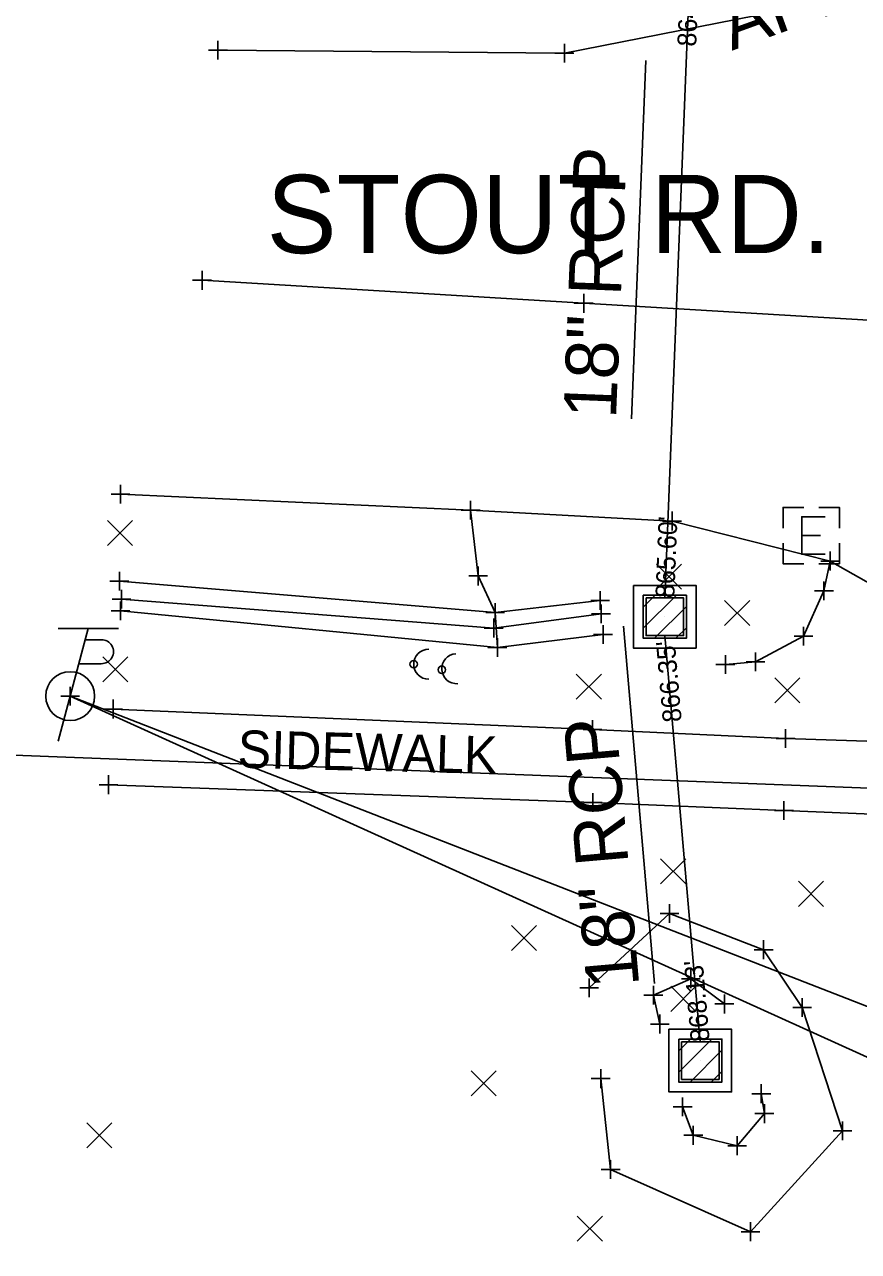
# Model space of a CAD drawing. Extents: x 1380550 to 1381945, y 468927 to 470496.
# Drawn here: x 1381538.1 to 1381582.5, y 470212.8 to 470278.1 of the extents above; entities that cross this region are included whole.
import ezdxf

# ---------------------------------------------------------------- set-up
doc = ezdxf.new("R2010")
doc.units = 0
for name, color, linetype in [('DR_X_Cells', 7, 'Continuous'), ('DR_X_Ditch', 7, 'Continuous'), ('DR_X_Storm_Sewer', 7, 'Continuous'), ('DR_X_Text', 7, 'Continuous'), ('GK_Drainage_Nodes', 7, 'Continuous'), ('HY_X_Water_Edge', 7, 'Continuous'), ('PV_X_COP', 7, 'Continuous'), ('PV_X_EOP', 7, 'Continuous'), ('PV_X_Walk', 7, 'Continuous'), ('RD_X_Text', 7, 'Continuous'), ('RW_X_Esmt_General', 7, 'Continuous'), ('SC_Scratch1', 7, 'Continuous'), ('SV_X_Random_Point', 7, 'Continuous'), ('SV_X_Shot_Marker', 7, 'Continuous'), ('SV_X_Toe_of_Slope', 7, 'Continuous'), ('SV_X_Top_of_Bank', 7, 'Continuous'), ('UT_X_Electric', 7, 'Continuous'), ('UT_X_Electric_Cells', 7, 'Continuous'), ('UT_X_Misc_Cells', 7, 'Continuous'), ('UT_X_Telecom', 7, 'Continuous')]:
    doc.layers.add(name, color=color, linetype=linetype)

msp = doc.modelspace()

# ---------------------------------------------------------------- linework, layer by layer
at = {"layer": 'DR_X_Cells'}
for p, q in [((1381571.02, 470245.963), (1381572.779, 470247.722)), ((1381571.02, 470247.094), (1381571.648, 470247.722)), ((1381571.619, 470245.43), (1381573.312, 470247.123)), ((1381572.75, 470245.43), (1381573.312, 470245.992)), ((1381572.908, 470222.344), (1381574.667, 470224.102)), ((1381572.908, 470223.475), (1381573.536, 470224.102)), ((1381573.507, 470221.811), (1381575.2, 470223.504)), ((1381574.638, 470221.811), (1381575.2, 470222.372))]:
    msp.add_line(p, q, dxfattribs=at)
for points in [[(1381570.499, 470248.243), (1381573.833, 470248.243), (1381573.833, 470244.909), (1381570.499, 470244.909)], [(1381571.02, 470247.722), (1381573.312, 470247.722), (1381573.312, 470245.43), (1381571.02, 470245.43)], [(1381571.166, 470247.576), (1381573.166, 470247.576), (1381573.166, 470245.576), (1381571.166, 470245.576)], [(1381572.387, 470224.623), (1381575.721, 470224.623), (1381575.721, 470221.29), (1381572.387, 470221.29)], [(1381572.908, 470224.102), (1381575.2, 470224.102), (1381575.2, 470221.811), (1381572.908, 470221.811)], [(1381573.054, 470223.957), (1381575.054, 470223.957), (1381575.054, 470221.957), (1381573.054, 470221.957)]]:
    msp.add_lwpolyline(points, close=True, dxfattribs=at)
at = {"layer": 'DR_X_Ditch'}
msp.add_lwpolyline([(1381543.263, 470247.518), (1381563.063, 470245.978), (1381568.771, 470246.733)], dxfattribs=at)
at = {"layer": 'DR_X_Storm_Sewer'}
for p, q in [((1381572.166, 470247.576), (1381573.515, 470281.557)), ((1381574.054, 470223.957), (1381572.166, 470245.576))]:
    msp.add_line(p, q, dxfattribs=at)
at = {"layer": 'DR_X_Text'}
for p, q in [((1381571.15, 470276.186), (1381570.393, 470257.114)), ((1381569.964, 470246.079), (1381571.624, 470227.065))]:
    msp.add_line(p, q, dxfattribs=at)
at = {"layer": 'GK_Drainage_Nodes'}
for p, q in [((1381572.166, 470248.243), (1381572.166, 470248.243)), ((1381572.166, 470247.576), (1381572.166, 470247.576)), ((1381571.166, 470246.576), (1381571.166, 470246.576)), ((1381572.166, 470246.576), (1381572.166, 470246.576)), ((1381572.166, 470246.576), (1381572.166, 470246.576)), ((1381572.166, 470246.576), (1381572.166, 470246.576)), ((1381573.166, 470246.576), (1381573.166, 470246.576)), ((1381572.166, 470245.576), (1381572.166, 470245.576)), ((1381572.166, 470244.909), (1381572.166, 470244.909)), ((1381574.054, 470224.623), (1381574.054, 470224.623)), ((1381574.054, 470223.957), (1381574.054, 470223.957)), ((1381573.054, 470222.957), (1381573.054, 470222.957)), ((1381574.054, 470222.957), (1381574.054, 470222.957)), ((1381574.054, 470222.957), (1381574.054, 470222.957)), ((1381574.054, 470222.957), (1381574.054, 470222.957)), ((1381575.054, 470222.957), (1381575.054, 470222.957)), ((1381574.054, 470221.957), (1381574.054, 470221.957)), ((1381574.054, 470221.29), (1381574.054, 470221.29))]:
    msp.add_line(p, q, dxfattribs=at)
at = {"layer": 'HY_X_Water_Edge'}
for points in [[(1381543.147, 470248.469), (1381563.136, 470246.797), (1381568.729, 470247.446)], [(1381543.21, 470246.894), (1381563.256, 470244.94), (1381568.879, 470245.63)]]:
    msp.add_lwpolyline(points, dxfattribs=at)
at = {"layer": 'PV_X_COP'}
msp.add_lwpolyline([(1381547.543, 470264.484), (1381567.85, 470263.258), (1381584.182, 470262.283), (1381603.07, 470261.395)], dxfattribs=at)
at = {"layer": 'PV_X_EOP'}
for points in [[(1381613.385, 470321.734), (1381611.102, 470303.299), (1381608.359, 470295.151), (1381605.01, 470289.924), (1381604.443, 470290.292), (1381597.807, 470284.691), (1381598.172, 470283.697), (1381591.29, 470281.389), (1381566.822, 470276.57), (1381548.391, 470276.726)], [(1381543.209, 470253.101), (1381561.835, 470252.251), (1381562.236, 470248.747), (1381563.136, 470246.797), (1381563.256, 470244.94), (1381568.879, 470245.63)], [(1381561.835, 470252.251), (1381572.55, 470251.671), (1381580.965, 470249.541)], [(1381575.388, 470244.04), (1381576.993, 470244.172), (1381579.545, 470245.54), (1381580.634, 470247.96), (1381580.965, 470249.541), (1381591.472, 470243.585), (1381595.246, 470241.001), (1381599.724, 470235.672), (1381603.295, 470229.192), (1381604.877, 470222.306), (1381604.1, 470201.731), (1381602.36, 470179.429), (1381598.627, 470125.511), (1381593.594, 470071.886), (1381589.534, 470020.646), (1381585.494, 469971.089), (1381582.039, 469928.84), (1381578.382, 469880.278), (1381576.859, 469862.024), (1381576.832, 469860.709), (1381576.155, 469857.385), (1381571.588, 469847.123), (1381563.138, 469838.251)]]:
    msp.add_lwpolyline(points, dxfattribs=at)
at = {"layer": 'PV_X_Walk'}
for points in [[(1381542.819, 470241.667), (1381568.313, 470240.569), (1381578.584, 470240.095), (1381584.519, 470239.902), (1381590.984, 470239.649), (1381591.472, 470243.585)], [(1381542.564, 470237.64), (1381568.337, 470236.695), (1381578.506, 470236.262), (1381584.487, 470236.02), (1381590.642, 470235.62), (1381587.955, 470203.415), (1381586.625, 470180.461), (1381581.932, 470126.464), (1381577.652, 470073.239), (1381573.197, 470021.541), (1381569.148, 469971.738), (1381565.643, 469929.65), (1381561.644, 469881.156), (1381560.457, 469867.318), (1381559.272, 469848.708), (1381558.347, 469840.136)]]:
    msp.add_lwpolyline(points, dxfattribs=at)
at = {"layer": 'RW_X_Esmt_General'}
msp.add_lwpolyline([(1381490.401, 469029.464), (1381590.199, 470237.184), (1380558.689, 470277.035)], dxfattribs=at)
at = {"layer": 'SV_X_Random_Point'}
for p, q in [((1381542.519, 470250.365), (1381543.853, 470251.7)), ((1381542.519, 470251.7), (1381543.853, 470250.365)), ((1381571.722, 470248.046), (1381573.056, 470249.381)), ((1381571.722, 470249.381), (1381573.056, 470248.046)), ((1381575.349, 470246.105), (1381576.683, 470247.44)), ((1381575.349, 470247.44), (1381576.683, 470246.105)), ((1381542.267, 470243.114), (1381543.601, 470244.449)), ((1381542.267, 470244.449), (1381543.601, 470243.114)), ((1381567.455, 470242.188), (1381568.789, 470243.523)), ((1381567.455, 470243.523), (1381568.789, 470242.188)), ((1381578.022, 470241.99), (1381579.356, 470243.325)), ((1381578.022, 470243.325), (1381579.356, 470241.99)), ((1381571.942, 470232.36), (1381573.276, 470233.695)), ((1381571.942, 470233.695), (1381573.276, 470232.36)), ((1381579.269, 470231.162), (1381580.603, 470232.497)), ((1381579.269, 470232.497), (1381580.603, 470231.162)), ((1381564, 470228.809), (1381565.334, 470230.144)), ((1381564, 470230.144), (1381565.334, 470228.809)), ((1381572.489, 470225.574), (1381573.823, 470226.909)), ((1381572.489, 470226.909), (1381573.823, 470225.574)), ((1381561.857, 470221.08), (1381563.191, 470222.415)), ((1381561.857, 470222.415), (1381563.191, 470221.08)), ((1381541.417, 470218.315), (1381542.751, 470219.65)), ((1381541.417, 470219.65), (1381542.751, 470218.315)), ((1381567.511, 470213.347), (1381568.845, 470214.682)), ((1381567.511, 470214.682), (1381568.845, 470213.347))]:
    msp.add_line(p, q, dxfattribs=at)
at = {"layer": 'SV_X_Shot_Marker'}
for p, q in [((1381548.391, 470277.226), (1381548.391, 470276.226)), ((1381566.822, 470277.07), (1381566.822, 470276.07)), ((1381547.891, 470276.726), (1381548.891, 470276.726)), ((1381548.391, 470276.726), (1381548.391, 470276.726)), ((1381566.322, 470276.57), (1381567.322, 470276.57)), ((1381566.822, 470276.57), (1381566.822, 470276.57)), ((1381547.043, 470264.484), (1381548.043, 470264.484)), ((1381547.543, 470264.984), (1381547.543, 470263.984)), ((1381547.543, 470264.484), (1381547.543, 470264.484)), ((1381567.85, 470263.758), (1381567.85, 470262.758)), ((1381567.35, 470263.258), (1381568.35, 470263.258)), ((1381567.85, 470263.258), (1381567.85, 470263.258)), ((1381543.209, 470253.601), (1381543.209, 470252.601)), ((1381542.709, 470253.101), (1381543.709, 470253.101)), ((1381543.209, 470253.101), (1381543.209, 470253.101)), ((1381561.835, 470252.751), (1381561.835, 470251.751)), ((1381561.835, 470252.751), (1381561.835, 470251.751)), ((1381561.335, 470252.251), (1381562.335, 470252.251)), ((1381561.335, 470252.251), (1381562.335, 470252.251)), ((1381561.835, 470252.251), (1381561.835, 470252.251)), ((1381561.835, 470252.251), (1381561.835, 470252.251)), ((1381572.55, 470252.171), (1381572.55, 470251.171)), ((1381572.05, 470251.671), (1381573.05, 470251.671)), ((1381572.55, 470251.671), (1381572.55, 470251.671)), ((1381580.965, 470250.041), (1381580.965, 470249.041)), ((1381580.965, 470250.041), (1381580.965, 470249.041)), ((1381580.965, 470250.041), (1381580.965, 470249.041)), ((1381580.465, 470249.541), (1381581.465, 470249.541)), ((1381580.465, 470249.541), (1381581.465, 470249.541)), ((1381580.465, 470249.541), (1381581.465, 470249.541)), ((1381580.965, 470249.541), (1381580.965, 470249.541)), ((1381580.965, 470249.541), (1381580.965, 470249.541)), ((1381580.965, 470249.541), (1381580.965, 470249.541)), ((1381543.147, 470248.969), (1381543.147, 470247.969)), ((1381561.736, 470248.747), (1381562.736, 470248.747)), ((1381562.236, 470249.247), (1381562.236, 470248.247)), ((1381562.236, 470248.747), (1381562.236, 470248.747)), ((1381542.647, 470248.469), (1381543.647, 470248.469)), ((1381543.147, 470248.469), (1381543.147, 470248.469)), ((1381580.634, 470248.46), (1381580.634, 470247.46)), ((1381580.634, 470248.46), (1381580.634, 470247.46)), ((1381542.763, 470247.518), (1381543.763, 470247.518)), ((1381543.21, 470247.394), (1381543.21, 470246.394)), ((1381543.263, 470248.018), (1381543.263, 470247.018)), ((1381543.263, 470247.518), (1381543.263, 470247.518)), ((1381568.229, 470247.446), (1381569.229, 470247.446)), ((1381568.729, 470247.946), (1381568.729, 470246.946)), ((1381568.729, 470247.446), (1381568.729, 470247.446)), ((1381580.134, 470247.96), (1381581.134, 470247.96)), ((1381580.134, 470247.96), (1381581.134, 470247.96)), ((1381580.634, 470247.96), (1381580.634, 470247.96)), ((1381580.634, 470247.96), (1381580.634, 470247.96)), ((1381542.71, 470246.894), (1381543.71, 470246.894)), ((1381543.21, 470246.894), (1381543.21, 470246.894)), ((1381562.636, 470246.797), (1381563.636, 470246.797)), ((1381562.636, 470246.797), (1381563.636, 470246.797)), ((1381563.136, 470247.297), (1381563.136, 470246.297)), ((1381563.136, 470247.297), (1381563.136, 470246.297)), ((1381563.136, 470246.797), (1381563.136, 470246.797)), ((1381563.136, 470246.797), (1381563.136, 470246.797)), ((1381568.771, 470247.233), (1381568.771, 470246.233)), ((1381563.063, 470246.478), (1381563.063, 470245.478)), ((1381568.271, 470246.733), (1381569.271, 470246.733)), ((1381568.771, 470246.733), (1381568.771, 470246.733)), ((1381568.879, 470246.13), (1381568.879, 470245.13)), ((1381568.879, 470246.13), (1381568.879, 470245.13)), ((1381562.563, 470245.978), (1381563.563, 470245.978)), ((1381563.063, 470245.978), (1381563.063, 470245.978)), ((1381563.256, 470245.44), (1381563.256, 470244.44)), ((1381563.256, 470245.44), (1381563.256, 470244.44)), ((1381568.379, 470245.63), (1381569.379, 470245.63)), ((1381568.379, 470245.63), (1381569.379, 470245.63)), ((1381568.879, 470245.63), (1381568.879, 470245.63)), ((1381568.879, 470245.63), (1381568.879, 470245.63)), ((1381579.045, 470245.54), (1381580.045, 470245.54)), ((1381579.545, 470246.04), (1381579.545, 470245.04)), ((1381579.545, 470245.54), (1381579.545, 470245.54)), ((1381562.756, 470244.94), (1381563.756, 470244.94)), ((1381562.756, 470244.94), (1381563.756, 470244.94)), ((1381563.256, 470244.94), (1381563.256, 470244.94)), ((1381563.256, 470244.94), (1381563.256, 470244.94)), ((1381575.388, 470244.54), (1381575.388, 470243.54)), ((1381576.493, 470244.172), (1381577.493, 470244.172)), ((1381576.493, 470244.172), (1381577.493, 470244.172)), ((1381576.993, 470244.672), (1381576.993, 470243.672)), ((1381576.993, 470244.672), (1381576.993, 470243.672)), ((1381576.993, 470244.172), (1381576.993, 470244.172)), ((1381576.993, 470244.172), (1381576.993, 470244.172)), ((1381574.888, 470244.04), (1381575.888, 470244.04)), ((1381575.388, 470244.04), (1381575.388, 470244.04)), ((1381540.532, 470242.854), (1381540.532, 470241.854)), ((1381540.532, 470242.854), (1381540.532, 470241.854)), ((1381540.032, 470242.354), (1381541.032, 470242.354)), ((1381540.032, 470242.354), (1381541.032, 470242.354)), ((1381540.532, 470242.354), (1381540.532, 470242.354)), ((1381540.532, 470242.354), (1381540.532, 470242.354)), ((1381542.319, 470241.667), (1381543.319, 470241.667)), ((1381542.819, 470242.167), (1381542.819, 470241.167)), ((1381542.819, 470241.667), (1381542.819, 470241.667)), ((1381568.313, 470241.069), (1381568.313, 470240.069)), ((1381567.813, 470240.569), (1381568.813, 470240.569)), ((1381568.313, 470240.569), (1381568.313, 470240.569)), ((1381578.584, 470240.595), (1381578.584, 470239.595)), ((1381578.084, 470240.095), (1381579.084, 470240.095)), ((1381578.584, 470240.095), (1381578.584, 470240.095)), ((1381542.064, 470237.64), (1381543.064, 470237.64)), ((1381542.564, 470238.14), (1381542.564, 470237.14)), ((1381542.564, 470237.64), (1381542.564, 470237.64)), ((1381568.337, 470237.195), (1381568.337, 470236.195)), ((1381567.837, 470236.695), (1381568.837, 470236.695)), ((1381568.337, 470236.695), (1381568.337, 470236.695)), ((1381578.506, 470236.762), (1381578.506, 470235.762)), ((1381578.006, 470236.262), (1381579.006, 470236.262)), ((1381578.506, 470236.262), (1381578.506, 470236.262)), ((1381572.411, 470231.282), (1381572.411, 470230.282)), ((1381571.911, 470230.782), (1381572.911, 470230.782)), ((1381572.411, 470230.782), (1381572.411, 470230.782)), ((1381577.422, 470229.357), (1381577.422, 470228.357)), ((1381577.422, 470229.357), (1381577.422, 470228.357)), ((1381576.922, 470228.857), (1381577.922, 470228.857)), ((1381576.922, 470228.857), (1381577.922, 470228.857)), ((1381577.422, 470228.857), (1381577.422, 470228.857)), ((1381577.422, 470228.857), (1381577.422, 470228.857)), ((1381573.547, 470227.807), (1381573.547, 470226.807)), ((1381568.146, 470227.329), (1381568.146, 470226.329)), ((1381568.146, 470227.329), (1381568.146, 470226.329)), ((1381568.146, 470227.329), (1381568.146, 470226.329)), ((1381573.047, 470227.307), (1381574.047, 470227.307)), ((1381573.547, 470227.307), (1381573.547, 470227.307)), ((1381567.646, 470226.829), (1381568.646, 470226.829)), ((1381567.646, 470226.829), (1381568.646, 470226.829)), ((1381567.646, 470226.829), (1381568.646, 470226.829)), ((1381568.146, 470226.829), (1381568.146, 470226.829)), ((1381568.146, 470226.829), (1381568.146, 470226.829)), ((1381568.146, 470226.829), (1381568.146, 470226.829)), ((1381571.558, 470226.936), (1381571.558, 470225.936)), ((1381571.558, 470226.936), (1381571.558, 470225.936)), ((1381571.058, 470226.436), (1381572.058, 470226.436)), ((1381571.058, 470226.436), (1381572.058, 470226.436)), ((1381571.558, 470226.436), (1381571.558, 470226.436)), ((1381571.558, 470226.436), (1381571.558, 470226.436)), ((1381574.834, 470225.969), (1381575.834, 470225.969)), ((1381574.834, 470225.969), (1381575.834, 470225.969)), ((1381575.334, 470226.469), (1381575.334, 470225.469)), ((1381575.334, 470226.469), (1381575.334, 470225.469)), ((1381575.334, 470225.969), (1381575.334, 470225.969)), ((1381575.334, 470225.969), (1381575.334, 470225.969)), ((1381579.474, 470226.279), (1381579.474, 470225.279)), ((1381571.905, 470225.4), (1381571.905, 470224.4)), ((1381578.974, 470225.779), (1381579.974, 470225.779)), ((1381579.474, 470225.779), (1381579.474, 470225.779)), ((1381571.405, 470224.9), (1381572.405, 470224.9)), ((1381571.905, 470224.9), (1381571.905, 470224.9)), ((1381568.253, 470221.996), (1381569.253, 470221.996)), ((1381568.753, 470222.496), (1381568.753, 470221.496)), ((1381568.753, 470221.996), (1381568.753, 470221.996)), ((1381577.3, 470221.693), (1381577.3, 470220.693)), ((1381573.112, 470220.999), (1381573.112, 470219.999)), ((1381576.8, 470221.193), (1381577.8, 470221.193)), ((1381577.3, 470221.193), (1381577.3, 470221.193)), ((1381577.462, 470220.633), (1381577.462, 470219.633)), ((1381577.462, 470220.633), (1381577.462, 470219.633)), ((1381572.612, 470220.499), (1381573.612, 470220.499)), ((1381573.112, 470220.499), (1381573.112, 470220.499)), ((1381576.962, 470220.133), (1381577.962, 470220.133)), ((1381576.962, 470220.133), (1381577.962, 470220.133)), ((1381577.462, 470220.133), (1381577.462, 470220.133)), ((1381577.462, 470220.133), (1381577.462, 470220.133)), ((1381573.682, 470219.479), (1381573.682, 470218.479)), ((1381573.682, 470219.479), (1381573.682, 470218.479)), ((1381581.621, 470219.715), (1381581.621, 470218.715)), ((1381581.621, 470219.715), (1381581.621, 470218.715)), ((1381573.182, 470218.979), (1381574.182, 470218.979)), ((1381573.182, 470218.979), (1381574.182, 470218.979)), ((1381573.682, 470218.979), (1381573.682, 470218.979)), ((1381573.682, 470218.979), (1381573.682, 470218.979)), ((1381576.019, 470218.926), (1381576.019, 470217.926)), ((1381581.121, 470219.215), (1381582.121, 470219.215)), ((1381581.121, 470219.215), (1381582.121, 470219.215)), ((1381581.621, 470219.215), (1381581.621, 470219.215)), ((1381581.621, 470219.215), (1381581.621, 470219.215)), ((1381575.519, 470218.426), (1381576.519, 470218.426)), ((1381576.019, 470218.426), (1381576.019, 470218.426)), ((1381569.282, 470217.657), (1381569.282, 470216.657)), ((1381569.282, 470217.657), (1381569.282, 470216.657)), ((1381568.782, 470217.157), (1381569.782, 470217.157)), ((1381568.782, 470217.157), (1381569.782, 470217.157)), ((1381569.282, 470217.157), (1381569.282, 470217.157)), ((1381569.282, 470217.157), (1381569.282, 470217.157)), ((1381576.726, 470214.348), (1381576.726, 470213.348)), ((1381576.226, 470213.848), (1381577.226, 470213.848)), ((1381576.726, 470213.848), (1381576.726, 470213.848))]:
    msp.add_line(p, q, dxfattribs=at)
at = {"layer": 'SV_X_Toe_of_Slope'}
for points in [[(1381571.905, 470224.9), (1381571.558, 470226.436), (1381573.547, 470227.307), (1381575.334, 470225.969)], [(1381577.3, 470221.193), (1381577.462, 470220.133), (1381576.019, 470218.426), (1381573.682, 470218.979), (1381573.112, 470220.499)]]:
    msp.add_lwpolyline(points, dxfattribs=at)
at = {"layer": 'SV_X_Top_of_Bank'}
msp.add_lwpolyline([(1381568.753, 470221.996), (1381569.282, 470217.157), (1381576.726, 470213.848), (1381581.621, 470219.215), (1381579.474, 470225.779), (1381577.422, 470228.857), (1381572.411, 470230.782), (1381568.146, 470226.829)], dxfattribs=at)
at = {"layer": 'UT_X_Electric'}
msp.add_lwpolyline([(1381595.795, 470220.833), (1381540.532, 470242.354)], dxfattribs=at)
at = {"layer": 'UT_X_Electric_Cells'}
for p, q in [((1381579.454, 470250.9), (1381580.454, 470250.9)), ((1381579.954, 470250.9), (1381579.954, 470250.9))]:
    msp.add_line(p, q, dxfattribs=at)
for points in [[(1381579.554, 470252.4), (1381578.454, 470252.4), (1381578.454, 470251.3)], [(1381581.454, 470251.3), (1381581.454, 470252.4), (1381580.354, 470252.4)], [(1381580.704, 470251.9), (1381579.454, 470251.9), (1381579.454, 470249.9), (1381580.704, 470249.9)], [(1381578.454, 470250.5), (1381578.454, 470249.4), (1381579.554, 470249.4)], [(1381580.354, 470249.4), (1381581.454, 470249.4), (1381581.454, 470250.5)]]:
    msp.add_lwpolyline(points, dxfattribs=at)
at = {"layer": 'UT_X_Misc_Cells'}
for p, q in [((1381541.495, 470245.954), (1381539.889, 470239.954)), ((1381543.095, 470245.954), (1381539.895, 470245.954)), ((1381541.335, 470245.354), (1381542.185, 470245.354)), ((1381540.994, 470244.079), (1381542.185, 470244.079))]:
    msp.add_line(p, q, dxfattribs=at)
for centre, radius in [((1381558.804, 470244.052), 0.2), ((1381540.532, 470242.354), 1.3), ((1381560.302, 470243.755), 0.2)]:
    msp.add_circle(centre, radius, dxfattribs=at)
for centre, radius, start, end in [((1381542.198, 470244.717), 0.638, 268.8767, 91.1233), ((1381559.604, 470244.052), 0.8, 90, 270), ((1381561.1, 470243.812), 0.8, 94.05406, 274.05406)]:
    msp.add_arc(centre, radius, start, end, dxfattribs=at)
at = {"layer": 'UT_X_Telecom'}
msp.add_lwpolyline([(1381595.346, 470217.51), (1381540.532, 470242.354)], dxfattribs=at)

# ---------------------------------------------------------------- texts
at = {"layer": 'DR_X_Text'}
for s, rotation, p in [('APPROX. DIR.', 19.95844, (1381575.732, 470276.697)), ('18" RCP', 87.7266, (1381569.567, 470257.087)), ('18" RCP', 94.9909, (1381570.809, 470226.934))]:
    msp.add_text(s, height=2.8, rotation=rotation, dxfattribs=at).set_placement(p)
at = {"layer": 'RD_X_Text'}
msp.add_text('STOUT RD.', height=4.1667, dxfattribs=at).set_placement((1381550.984, 470265.927))
msp.add_text('SIDEWALK', height=2, rotation=358.59482, dxfattribs=at).set_placement((1381549.42, 470238.543))
at = {"layer": 'SC_Scratch1'}
for s, rotation, p in [("864.50'", 87.7266, (1381573.831, 470276.908)), ("865.60'", 87.7266, (1381572.666, 470247.556)), ("866.35'", 94.9909, (1381573.067, 470241.005)), ("868.13'", 94.9909, (1381574.552, 470224))]:
    msp.add_text(s, height=1, rotation=rotation, dxfattribs=at).set_placement(p)

doc.saveas('drawing.dxf')
